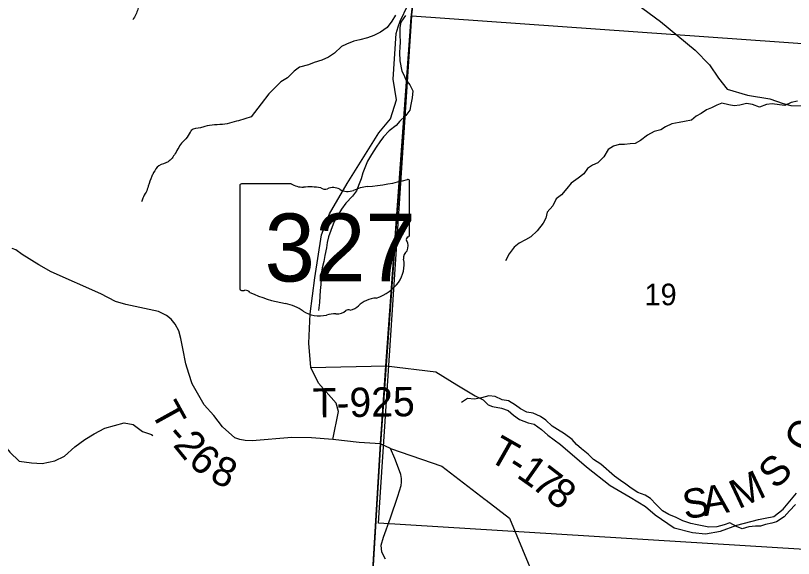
# Model space of a CAD drawing. Extents: x -13.1 to 43.1, y 0 to 22.
# Drawn here: x 6.242 to 7.753, y 18.795 to 19.849 of the extents above; entities that cross this region are included whole.
import ezdxf

# ---------------------------------------------------------------- set-up
doc = ezdxf.new("R2010")
doc.units = 0
for name, color, linetype in [('GM_X_Corporation', 7, 'Continuous'), ('GM_X_Minor_River', 7, 'Continuous'), ('GM_X_Section_Text', 7, 'Continuous'), ('GM_X_State_Location', 7, 'Continuous'), ('GM_X_State_Route', 7, 'Continuous'), ('GM_X_State_Shield', 7, 'Continuous'), ('GM_X_Township_Road', 7, 'Continuous'), ('GM_X_Township_Road_Text', 7, 'Continuous')]:
    doc.layers.add(name, color=color, linetype=linetype)

msp = doc.modelspace()

# ---------------------------------------------------------------- linework, layer by layer
at = {"layer": 'GM_X_Corporation'}
for points in [[(7.0807, 20.9), (2.1, 20.9), (2.1, 14.1), (6.6193, 14.1), (6.6994, 15.2069), (6.7531, 15.956), (6.8236, 16.9075), (6.9509, 19.0179), (7.0108, 19.8446), (7.0164, 19.8954), (7.0617, 20.6133)], [(7.0804, 20.9), (2.1, 20.9), (2.1, 14.1), (6.619, 14.1), (6.6992, 15.2074), (6.7528, 15.9566), (6.8234, 16.908), (6.8365, 17.1257), (6.9507, 19.0184), (6.9616, 19.1692), (7.0106, 19.8452), (7.0162, 19.896), (7.0615, 20.6138)], [(7.0804, 20.9), (2.1, 20.9), (2.1, 17.2152), (2.1437, 17.2135), (2.8442, 17.1637), (3.8328, 17.0966), (4.4304, 17.0575), (6.8234, 16.908), (6.8365, 17.1257), (6.9507, 19.0184), (6.9616, 19.1692), (7.0106, 19.8452), (7.0162, 19.896), (7.0615, 20.6138)], [(8.9, 15.7487), (8.9, 20.9), (7.0804, 20.9), (7.0615, 20.6138), (7.0162, 19.896), (7.0106, 19.8452), (6.9616, 19.1692), (6.9507, 19.0184), (6.8365, 17.1257), (6.8234, 16.908), (6.7528, 15.9566), (7.8612, 15.855), (8.7782, 15.7572)], [(8.9, 15.7487), (8.9, 20.9), (7.0804, 20.9), (7.0615, 20.6138), (7.0162, 19.896), (7.0106, 19.8452), (6.9616, 19.1692), (6.9507, 19.0184), (6.8365, 17.1257), (6.8234, 16.908), (6.7528, 15.9566), (7.8612, 15.855), (8.7782, 15.7572)], [(8.9, 15.7481), (8.9, 20.9), (7.0807, 20.9), (7.0617, 20.6133), (7.0164, 19.8954), (7.0108, 19.8446), (6.9509, 19.0179), (6.8236, 16.9075), (6.7531, 15.956), (7.8614, 15.8545), (8.7784, 15.7567)], [(7.0116, 19.8485), (8.018, 19.7768), (8.0053, 18.7983), (6.947, 18.8637), (6.949, 18.894)]]:
    msp.add_lwpolyline(points, close=True, dxfattribs=at)
at = {"layer": 'GM_X_Minor_River'}
for p, q in [((6.9922, 19.7411), (6.9962, 19.7337)), ((6.9962, 19.7337), (7.0003, 19.7242)), ((7.0003, 19.7242), (7.0082, 19.7146)), ((7.0082, 19.7146), (7.0138, 19.7025)), ((7.0138, 19.7025), (7.0126, 19.6892)), ((7.0126, 19.6892), (7.0102, 19.6759)), ((7.0102, 19.6759), (7.0079, 19.6653)), ((7.6044, 19.6747), (7.5941, 19.6699)), ((7.6142, 19.6785), (7.6044, 19.6747)), ((7.6275, 19.6757), (7.6142, 19.6785)), ((7.6381, 19.6738), (7.6275, 19.6757)), ((7.6487, 19.6748), (7.6381, 19.6738)), ((7.6616, 19.6778), (7.6487, 19.6748)), ((7.6737, 19.6762), (7.6616, 19.6778)), ((7.6873, 19.6712), (7.6737, 19.6762)), ((7.7006, 19.6764), (7.6873, 19.6712)), ((7.7116, 19.6775), (7.7006, 19.6764)), ((7.7259, 19.6755), (7.7116, 19.6775)), ((7.7365, 19.6739), (7.7259, 19.6755)), ((7.7487, 19.6799), (7.7365, 19.6739)), ((7.7612, 19.6825), (7.7487, 19.6799)), ((7.0079, 19.6653), (7.0002, 19.6551)), ((7.574, 19.6586), (7.5644, 19.6534)), ((7.5842, 19.6658), (7.574, 19.6586)), ((7.5941, 19.6699), (7.5842, 19.6658)), ((6.988, 19.6431), (6.9855, 19.6401)), ((7.0002, 19.6551), (6.988, 19.6431)), ((7.5417, 19.6429), (7.531, 19.6411)), ((7.5549, 19.6455), (7.5417, 19.6429)), ((7.5644, 19.6534), (7.5549, 19.6455)), ((7.4953, 19.6273), (7.4828, 19.6236)), ((7.5048, 19.6325), (7.4953, 19.6273)), ((7.517, 19.6385), (7.5048, 19.6325)), ((7.531, 19.6411), (7.517, 19.6385)), ((7.4699, 19.6164), (7.4562, 19.6063)), ((7.4828, 19.6236), (7.4699, 19.6164)), ((7.4148, 19.5982), (7.4038, 19.5956)), ((7.4247, 19.5985), (7.4148, 19.5982)), ((7.4361, 19.6), (7.4247, 19.5985)), ((7.4459, 19.6007), (7.4361, 19.6)), ((7.4562, 19.6063), (7.4459, 19.6007)), ((7.3932, 19.5885), (7.3848, 19.5749)), ((7.4038, 19.5956), (7.3932, 19.5885)), ((7.3848, 19.5749), (7.3733, 19.5628)), ((7.3532, 19.552), (7.3459, 19.5418)), ((7.3627, 19.5583), (7.3532, 19.552)), ((7.3733, 19.5628), (7.3627, 19.5583)), ((7.3459, 19.5418), (7.3348, 19.5331)), ((7.3211, 19.5237), (7.3127, 19.5132)), ((7.3348, 19.5331), (7.3211, 19.5237)), ((7.3127, 19.5132), (7.3024, 19.5007)), ((7.2921, 19.4932), (7.286, 19.4792)), ((7.3024, 19.5007), (7.2921, 19.4932)), ((7.286, 19.4792), (7.2745, 19.4675)), ((7.2745, 19.4675), (7.2718, 19.4558)), ((7.2668, 19.4456), (7.2553, 19.4308)), ((7.2718, 19.4558), (7.2668, 19.4456)), ((7.2553, 19.4308), (7.2428, 19.4192)), ((7.2428, 19.4192), (7.2329, 19.4135)), ((7.2203, 19.4072), (7.2104, 19.3993)), ((7.2329, 19.4135), (7.2203, 19.4072)), ((7.2009, 19.3861), (7.1939, 19.3728)), ((7.2104, 19.3993), (7.2009, 19.3861))]:
    msp.add_line(p, q, dxfattribs=at)
for points in [[(6.9803, 19.8495), (6.9731, 19.8381), (6.9637, 19.8255), (6.9512, 19.8168), (6.938, 19.8103), (6.9255, 19.8053), (6.9107, 19.8015), (6.8994, 19.7988), (6.885, 19.7934), (6.8751, 19.7885), (6.8619, 19.7759), (6.8498, 19.7683), (6.8369, 19.7622), (6.8222, 19.7576), (6.8112, 19.7534), (6.7938, 19.7488), (6.7832, 19.7411), (6.7703, 19.7278), (6.7571, 19.7202), (6.7458, 19.7084), (6.7344, 19.697), (6.7189, 19.6774), (6.6998, 19.652)], [(6.9994, 19.8489), (6.9906, 19.8359), (6.9883, 19.8256), (6.9887, 19.8112), (6.9891, 19.7972), (6.9888, 19.7877), (6.9877, 19.777), (6.9885, 19.7611), (6.9922, 19.7411)], [(6.9855, 19.6401), (6.9811, 19.6355), (6.9675, 19.6252), (6.9569, 19.6134), (6.9494, 19.6039), (6.9426, 19.5933), (6.9335, 19.5788), (6.926, 19.5659), (6.9203, 19.553), (6.9169, 19.5435), (6.9132, 19.5321), (6.9094, 19.5219), (6.9045, 19.5089), (6.8966, 19.4983), (6.8834, 19.4846), (6.8754, 19.4732), (6.8683, 19.4614), (6.8611, 19.4489), (6.8547, 19.4314), (6.8498, 19.4196), (6.8475, 19.4082), (6.846, 19.398), (6.8427, 19.3832), (6.8408, 19.3714), (6.8378, 19.3589), (6.8359, 19.3471), (6.8359, 19.3376), (6.8352, 19.327), (6.8337, 19.3149), (6.8334, 19.3042), (6.8323, 19.2921), (6.8304, 19.2765)], [(7.757, 18.9), (7.7456, 18.8875), (7.7349, 18.8759), (7.7204, 18.8661), (7.711, 18.8639), (7.6988, 18.8613), (7.6889, 18.858), (7.6791, 18.858), (7.6666, 18.8566), (7.6533, 18.8529), (7.6424, 18.8571), (7.6295, 18.8644), (7.6185, 18.8603), (7.6041, 18.8566), (7.589, 18.8556), (7.5757, 18.8583), (7.5659, 18.8603), (7.5538, 18.863), (7.5383, 18.868), (7.5251, 18.8746), (7.5111, 18.8803), (7.4987, 18.8876), (7.4867, 18.9002), (7.4754, 18.9117), (7.4652, 18.9178), (7.4508, 18.9232), (7.4377, 18.9313), (7.4275, 18.9393), (7.4173, 18.9462), (7.4053, 18.955), (7.3789, 18.9779), (7.365, 18.9875), (7.3544, 18.9978), (7.3416, 19.0081), (7.3319, 19.0162), (7.3232, 19.0261), (7.3085, 19.0368), (7.2946, 19.0452), (7.2844, 19.0517), (7.2724, 19.0636), (7.2618, 19.0709), (7.2475, 19.0774), (7.235, 19.0794), (7.2229, 19.0855), (7.2131, 19.0924), (7.1999, 19.1008), (7.1871, 19.1028), (7.1735, 19.1094), (7.1617, 19.1106), (7.1473, 19.1072), (7.1337, 19.1043), (7.1197, 19.1059), (7.1083, 19.098)], [(6.2056, 19.0434), (6.2145, 19.0221), (6.231, 19.0015), (6.249, 18.9839), (6.2732, 18.9806), (6.2936, 18.9797), (6.3187, 18.9848), (6.3369, 18.9938), (6.3575, 19.0118), (6.3765, 19.0261), (6.3948, 19.0373), (6.4153, 19.0478), (6.4533, 19.0581), (6.4707, 19.0549), (6.4887, 19.0418), (6.5061, 19.0356), (6.5091, 19.0341)]]:
    msp.add_lwpolyline(points, dxfattribs=at)
for points in [[(6.554, 20.3961), (6.5856, 20.3862), (6.5873, 20.3627), (6.5876, 20.3491), (6.5867, 20.3223), (6.5851, 20.3098), (6.5823, 20.2879), (6.5815, 20.2811), (6.5833, 20.2709), (6.5844, 20.2622), (6.5862, 20.2531), (6.5917, 20.2273), (6.5924, 20.2163), (6.5979, 20.189), (6.6004, 20.1803), (6.6033, 20.1576), (6.6036, 20.147), (6.6031, 20.1254), (6.6026, 20.1163), (6.6006, 20.0967), (6.5964, 20.0866), (6.5902, 20.0662), (6.5803, 20.0539), (6.5784, 20.0471), (6.5711, 20.0313), (6.5626, 20.0065), (6.5595, 19.9982), (6.5541, 19.982), (6.5511, 19.9757), (6.5438, 19.9591), (6.5396, 19.949), (6.5277, 19.9238), (6.5189, 19.9088), (6.5017, 19.8849), (6.4938, 19.877), (6.4824, 19.8696), (6.4797, 19.8614), (6.4701, 19.8407)], [(6.6998, 19.652), (6.6669, 19.6424), (6.6488, 19.6381), (6.6095, 19.6334), (6.6015, 19.6309), (6.5834, 19.6254), (6.5815, 19.6224), (6.5731, 19.6097), (6.567, 19.6037), (6.5521, 19.5809), (6.5384, 19.5652), (6.5206, 19.5571), (6.5103, 19.544), (6.5069, 19.5369), (6.5, 19.5177), (6.4957, 19.5061), (6.4892, 19.4941), (6.4881, 19.4903), (6.4869, 19.4873)]]:
    msp.add_spline(points, degree=3, dxfattribs=at)
at = {"layer": 'GM_X_State_Route'}
for points in [[(6.9509, 19.0179), (6.9094, 19.0202), (6.8585, 19.0258), (6.8695, 19.0801), (6.8649, 19.0964), (6.8307, 19.1354), (6.8159, 19.166), (6.812, 19.2128), (6.8146, 19.2697), (6.8236, 19.34), (6.8367, 19.4232), (6.8518, 19.4638), (6.8862, 19.5228), (6.9475, 19.6212), (6.9706, 19.6483), (6.9819, 19.6851), (6.9758, 19.7253), (6.9812, 19.8142), (6.9853, 19.8269), (6.9889, 19.8377), (7.0038, 19.8689), (7.0094, 19.8835), (7.0164, 19.8954)], [(6.9605, 18.7939), (6.9538, 18.8076), (6.9521, 18.8209), (6.9568, 18.8368), (6.9704, 18.8742), (6.9847, 18.9158), (6.991, 18.937), (6.9921, 18.9431), (6.9919, 18.9503), (6.9904, 18.9583), (6.9882, 18.9655), (6.9786, 18.9891), (6.9703, 19.0085), (6.9509, 19.0179)]]:
    msp.add_lwpolyline(points, dxfattribs=at)
at = {"layer": 'GM_X_State_Shield'}
for p, q in [((6.7776, 19.5222), (6.6811, 19.5222)), ((7.0075, 19.4225), (7.0075, 19.5272)), ((6.6779, 19.5187), (6.6779, 19.3186)), ((7.0074, 19.4225), (7.0075, 19.4225))]:
    msp.add_line(p, q, dxfattribs=at)
for centre, major_axis, start_param, end_param in [((6.6817, 19.5192), (0.00382, 0), 1.712693, 3.28349), ((6.8006, 19.5454), (0.037, 0), 4.042523, 4.731795), ((6.8901, 19.795), (0.3495, 0), 4.814394, 5.042369), ((7.0038, 19.5276), (0.00367, 0), 6.141152, 7.989035), ((6.8129, 19.4098), (0.133, 0), 1.404758, 1.657858), ((6.8431, 19.5202), (0.0107, 0), 3.836095, 5.185415), ((6.8588, 19.4971), (0.0222, 0), 0.950623, 2.079405), ((6.8875, 19.5288), (0.0267, 0), 4.081561, 5.145723), ((6.9346, 19.4611), (0.0703, 0), 1.699011, 2.107814), ((7.0066, 19.4148), (0.00568, 0), 1.883978, 3.671073), ((7.0036, 19.4221), (0.00393, 0), 5.05454, 6.418171), ((6.9705, 19.4015), (0.0341, 0), 5.934695, 6.695948), ((7.0206, 19.3787), (0.0248, 0), 2.387724, 3.262537), ((6.9096, 19.3653), (0.0874, 0), 5.101752, 6.440018), ((6.6817, 19.3182), (0.00385, 0), 3.00124, 4.508301), ((6.6823, 19.3387), (0.0294, 0), 4.665946, 4.897461), ((6.6883, 19.3071), (0.0106, 0), 0.519207, 1.627899), ((6.8221, 19.4869), (0.2524, 0), 4.195997, 4.488961), ((6.9465, 19.2624), (0.0479, 0), 1.647645, 2.488434), ((6.7469, 19.2287), (0.079, 0), 0.823519, 1.323587), ((6.8858, 19.2992), (0.0282, 0), 4.937069, 5.64225), ((6.8323, 19.3061), (0.0501, 0), 4.026481, 4.996735), ((6.8612, 19.2369), (0.0412, 0), 1.495662, 1.94098), ((6.8649, 19.2911), (0.0267, 0), 4.691044, 5.507374), ((6.889, 19.2717), (0.00752, 0), 1.147584, 2.315152)]:
    msp.add_ellipse(centre, major_axis=major_axis, ratio=0.8, start_param=start_param, end_param=end_param, dxfattribs=at)
at = {"layer": 'GM_X_Township_Road'}
msp.add_line((6.8159, 19.166), (6.9618, 19.1687), dxfattribs=at)
for points in [[(7.4482, 19.8714), (7.4948, 19.8372), (7.5621, 19.7819), (7.59, 19.7532), (7.6073, 19.7275), (7.6245, 19.706), (7.6641, 19.6941), (7.7071, 19.6869), (7.7334, 19.6783), (7.7478, 19.6739), (7.7752, 19.6733)], [(6.8585, 19.0258), (6.8168, 19.0292), (6.7789, 19.0301), (6.7018, 19.0232), (6.6881, 19.0241), (6.6775, 19.0262), (6.6681, 19.0293), (6.6441, 19.0509), (6.6273, 19.0728), (6.6086, 19.0932), (6.5979, 19.1116), (6.5853, 19.1341), (6.5784, 19.1543), (6.5726, 19.1726), (6.5673, 19.2027), (6.5634, 19.2221), (6.559, 19.2366), (6.5524, 19.2496), (6.5446, 19.2596), (6.5352, 19.2666), (6.5197, 19.2744), (6.4562, 19.2882), (6.4365, 19.2941), (6.4075, 19.3089), (6.311, 19.3513), (6.2873, 19.3653), (6.2553, 19.3851), (6.2429, 19.394), (6.2354, 19.3964)], [(6.9618, 19.1687), (7.0583, 19.1575), (7.0991, 19.132), (7.1346, 19.1106), (7.1506, 19.1028), (7.1598, 19.0934), (7.1686, 19.0904), (7.1857, 19.0871), (7.199, 19.0822), (7.209, 19.0732), (7.2212, 19.0646), (7.2376, 19.0586), (7.2494, 19.0557), (7.2639, 19.0455), (7.2757, 19.0342), (7.3005, 19.0162), (7.351, 18.9729), (7.3972, 18.9368), (7.4358, 18.9143), (7.4655, 18.8959), (7.4842, 18.8801), (7.5217, 18.8549), (7.5567, 18.8453), (7.5821, 18.8428), (7.6117, 18.8484), (7.6428, 18.86), (7.6849, 18.8709), (7.6982, 18.8733), (7.7152, 18.8765), (7.733, 18.8911), (7.759, 18.9216)], [(6.9703, 19.0085), (7.07, 18.9746), (7.1544, 18.9095), (7.156, 18.9083)], [(7.156, 18.9083), (7.2015, 18.8732), (7.2522, 18.7515), (7.2821, 18.6786), (7.3145, 18.6538), (7.3425, 18.6486), (7.3849, 18.6505), (7.4515, 18.6029), (7.4742, 18.5985), (7.571, 18.62), (7.6069, 18.5792), (7.6089, 18.577)]]:
    msp.add_lwpolyline(points, dxfattribs=at)

# ---------------------------------------------------------------- texts
at = {"layer": 'GM_X_Section_Text'}
msp.add_text('19', height=0.04186, rotation=0, dxfattribs=at).set_placement((7.4639, 19.2866))
at = {"layer": 'GM_X_State_Location'}
for s in ['s', 'r']:
    msp.add_text(s, height=0.000189, dxfattribs=at).set_placement((6.839, 19.4054))
msp.add_text('327', height=0.000189, rotation=0, dxfattribs=at).set_placement((6.7721, 19.3916))
at = {"layer": 'GM_X_State_Shield'}
msp.add_text('327', height=0.13184, dxfattribs=at).set_placement((6.7257, 19.3327))
at = {"layer": 'GM_X_Township_Road_Text'}
for s, height, rotation, p in [('T-925', 0.05682, 0.8421, (6.8194, 19.0685)), ('T', 0.0568, 298.973, (6.5034, 19.08)), ('C', 0.0568, 61.525, (7.7818, 18.9963)), ('-', 0.0568, 311.2856, (6.5316, 19.0319)), ('2', 0.0568, 309.1979, (6.5466, 19.0148)), ('T', 0.0568, 330.3189, (7.1577, 18.9869)), ('6', 0.0568, 317.4625, (6.5749, 18.9812)), ('8', 0.0568, 335.676, (6.617, 18.9467)), ('S', 0.0568, 43.3549, (7.7182, 18.9275)), ('-', 0.0568, 327.4618, (7.194, 18.9663)), ('1', 0.0568, 324.8809, (7.2131, 18.9541)), ('7', 0.0568, 322.5098, (7.2412, 18.9343)), ('M', 0.0568, 25.2527, (7.6463, 18.8901)), ('8', 0.0568, 321.5312, (7.2688, 18.9132)), ('S', 0.0568, 8.8444, (7.5421, 18.8711)), ('A', 0.0568, 9.148, (7.5803, 18.8771))]:
    msp.add_text(s, height=height, rotation=rotation, dxfattribs=at).set_placement(p)

doc.saveas('drawing.dxf')
